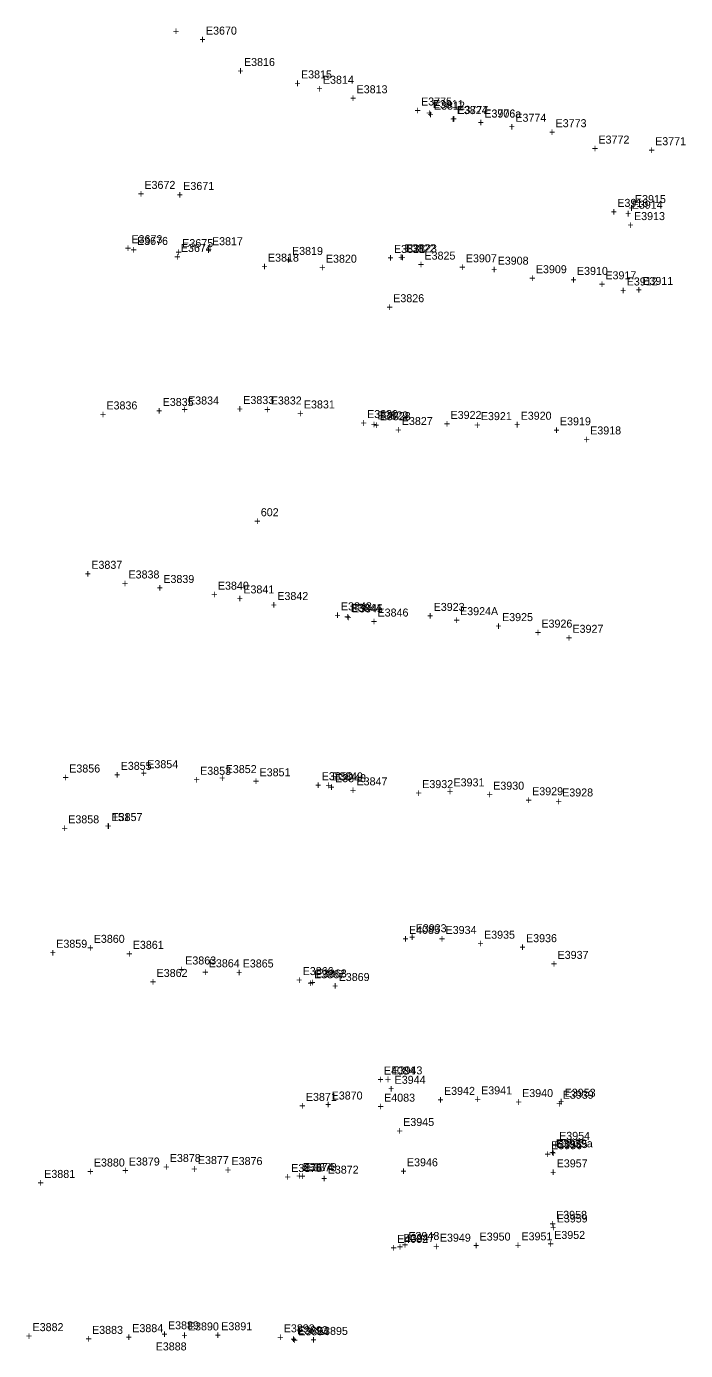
# Model space of a CAD drawing. Extents: x 1667192 to 1669644, y 336680 to 339991.
# Drawn here: x 1667196.6 to 1667402.6, y 337507.8 to 337921.4 of the extents above; entities that cross this region are included whole.
import ezdxf

# ---------------------------------------------------------------- set-up
doc = ezdxf.new("R2010")
doc.units = 0
for name, color, linetype in [('S_Control_Temp_Traverse', 7, 'Continuous'), ('S_Curb_Type_3', 7, 'Continuous'), ('S_Curb_Type_5', 7, 'Continuous'), ('S_Drainage_CB', 7, 'Continuous'), ('S_Ground_Elevation', 7, 'Continuous'), ('S_Guardrail_Beam', 7, 'Continuous'), ('S_Roadway_Edge_Pavement', 7, 'Continuous'), ('S_Roadway_Edge_TW', 7, 'Continuous'), ('S_Traffic_Sign_SinglePost', 7, 'Continuous'), ('S_Utilities_GuyWire3', 7, 'Continuous'), ('S_Utilities_Pole_Power', 7, 'Continuous')]:
    doc.layers.add(name, color=color, linetype=linetype)

msp = doc.modelspace()

# ---------------------------------------------------------------- texts
at = {"layer": 'S_Control_Temp_Traverse'}
for s, p in [('+', (1667267.8, 337765.64)), ('+', (1667267.8, 337765.64)), ('+', (1667267.8, 337765.64)), ('+', (1667267.8, 337765.64)), ('+', (1667267.8, 337765.64)), ('+', (1667267.8, 337765.64)), ('+', (1667267.8, 337765.64)), ('+', (1667267.8, 337765.64)), ('602', (1667269.86, 337768.39)), ('602', (1667269.86, 337768.39)), ('602', (1667269.86, 337768.39)), ('602', (1667269.86, 337768.39)), ('602', (1667269.86, 337768.39)), ('602', (1667269.86, 337768.39)), ('602', (1667269.86, 337768.39)), ('602', (1667269.86, 337768.39)), ('151', (1667223.37, 337673.16)), ('+', (1667221.31, 337670.41))]:
    msp.add_text(s, height=2.5, dxfattribs=at).set_placement(p)
at = {"layer": 'S_Curb_Type_3'}
for s, p in [('E3955', (1667362.31, 337571.02)), ('+', (1667360.25, 337568.27)), ('E3959', (1667362.32, 337547.79)), ('+', (1667360.26, 337545.04))]:
    msp.add_text(s, height=2.5, dxfattribs=at).set_placement(p)
at = {"layer": 'S_Curb_Type_5'}
for s, p in [('E3812', (1667323.96, 337895.39)), ('+', (1667321.9, 337892.64)), ('E3823', (1667315.22, 337850.78)), ('+', (1667313.16, 337848.03)), ('E3828', (1667307.01, 337798.39)), ('+', (1667304.95, 337795.64)), ('E3845', (1667298.32, 337738.34)), ('+', (1667296.26, 337735.59)), ('E3848', (1667293.05, 337685.32)), ('+', (1667290.99, 337682.57)), ('+', (1667284.97, 337621.56)), ('E3868', (1667287.03, 337624.31)), ('E3873', (1667283.92, 337563.79)), ('+', (1667281.86, 337561.04)), ('+', (1667279.49, 337509.8)), ('E3894', (1667281.55, 337512.55))]:
    msp.add_text(s, height=2.5, dxfattribs=at).set_placement(p)
at = {"layer": 'S_Drainage_CB'}
for s, p in [('E3915', (1667386.77, 337866.21)), ('+', (1667384.71, 337863.46)), ('+', (1667309.18, 337832.49)), ('E3826', (1667311.24, 337835.24)), ('E3871', (1667283.94, 337585.75)), ('E3870', (1667292, 337586.19)), ('+', (1667281.88, 337583)), ('+', (1667289.94, 337583.44)), ('+', (1667358.51, 337567.93)), ('E3956', (1667360.57, 337570.68))]:
    msp.add_text(s, height=2.5, dxfattribs=at).set_placement(p)
at = {"layer": 'S_Ground_Elevation'}
for s, p in [('+', (1667242.38, 337918.66)), ('E3670', (1667252.72, 337918.83)), ('+', (1667250.66, 337916.08)), ('+', (1667262.54, 337906.27)), ('E3816', (1667264.6, 337909.02)), ('+', (1667280.36, 337902.4)), ('E3815', (1667282.42, 337905.15)), ('E3824', (1667331.06, 337894)), ('E3777', (1667331.27, 337894.08)), ('+', (1667329, 337891.25)), ('+', (1667329.21, 337891.33)), ('E3672', (1667233.49, 337870.63)), ('E3671', (1667245.63, 337870.31)), ('+', (1667231.43, 337867.88)), ('+', (1667243.57, 337867.56)), ('E3673', (1667229.44, 337853.67)), ('E3817', (1667254.6, 337853.05)), ('+', (1667227.38, 337850.92)), ('E3674', (1667244.88, 337850.94)), ('+', (1667252.54, 337850.3)), ('E3818', (1667272.09, 337847.91)), ('E3825', (1667321, 337848.55)), ('+', (1667242.82, 337848.19)), ('+', (1667270.03, 337845.16)), ('+', (1667318.94, 337845.8)), ('E3835', (1667239.19, 337802.83)), ('E3834', (1667247.13, 337803.29)), ('E3833', (1667264.38, 337803.44)), ('+', (1667219.56, 337799)), ('E3836', (1667221.62, 337801.75)), ('+', (1667237.13, 337800.08)), ('+', (1667245.07, 337800.54)), ('+', (1667262.32, 337800.69)), ('E3827', (1667313.92, 337796.88)), ('+', (1667311.85, 337794.13)), ('+', (1667214.84, 337749.21)), ('E3837', (1667216.9, 337751.96)), ('E3838', (1667228.52, 337748.95)), ('+', (1667226.46, 337746.2)), ('E3839', (1667239.4, 337747.54)), ('E3840', (1667256.45, 337745.45)), ('+', (1667237.34, 337744.79)), ('+', (1667254.39, 337742.7)), ('E3846', (1667306.33, 337737.05)), ('+', (1667304.27, 337734.3)), ('E3856', (1667210, 337688.34)), ('E3855', (1667226.07, 337689.17)), ('E3854', (1667234.38, 337689.68)), ('E3853', (1667250.9, 337687.62)), ('+', (1667207.94, 337685.59)), ('+', (1667224.01, 337686.42)), ('+', (1667232.32, 337686.93)), ('+', (1667248.84, 337684.87)), ('E3847', (1667299.76, 337684.32)), ('+', (1667297.7, 337681.57)), ('E4085', (1667316.16, 337637.91)), ('E3859', (1667205.95, 337633.6)), ('E3860', (1667217.66, 337635.13)), ('E3861', (1667229.85, 337633.26)), ('+', (1667314.1, 337635.17)), ('+', (1667203.89, 337630.85)), ('+', (1667215.6, 337632.38)), ('+', (1667227.79, 337630.51)), ('+', (1667244.18, 337625.62)), ('E3863', (1667246.24, 337628.37)), ('E3869', (1667294.18, 337623.21)), ('+', (1667292.12, 337620.46)), ('E4084', (1667308.33, 337593.97)), ('+', (1667306.27, 337591.22)), ('E4083', (1667308.39, 337585.53)), ('+', (1667306.33, 337582.78)), ('E3880', (1667217.69, 337565.26)), ('E3879', (1667228.62, 337565.58)), ('+', (1667239.36, 337563.92)), ('E3878', (1667241.42, 337566.67)), ('E3872', (1667290.76, 337563.04)), ('+', (1667200.13, 337558.95)), ('E3881', (1667202.19, 337561.7)), ('+', (1667215.63, 337562.51)), ('+', (1667226.56, 337562.83)), ('+', (1667288.7, 337560.29)), ('+', (1667310.4, 337538.67)), ('E4082', (1667312.47, 337541.42)), ('E3882', (1667198.54, 337513.84)), ('E3883', (1667217.13, 337512.98)), ('E3884', (1667229.7, 337513.52)), ('E3889', (1667240.86, 337514.42)), ('+', (1667196.48, 337511.09)), ('+', (1667215.07, 337510.23)), ('+', (1667227.64, 337510.77)), ('+', (1667238.8, 337511.67)), ('+', (1667285.34, 337509.91)), ('E3895', (1667287.4, 337512.66))]:
    msp.add_text(s, height=2.5, dxfattribs=at).set_placement(p)
at = {"layer": 'S_Guardrail_Beam'}
for s, p in [('+', (1667309.61, 337588.35)), ('E3944', (1667311.67, 337591.1)), ('+', (1667362.75, 337584.31)), ('E3953', (1667364.81, 337587.06)), ('E3945', (1667314.35, 337577.92)), ('+', (1667312.29, 337575.17)), ('E3954', (1667363.07, 337573.59)), ('+', (1667361.01, 337570.84)), ('E3946', (1667315.52, 337565.34)), ('E3957', (1667362.31, 337565)), ('+', (1667313.46, 337562.59)), ('+', (1667360.25, 337562.25)), ('E3958', (1667362.12, 337548.92)), ('E3948', (1667315.98, 337542.32)), ('+', (1667360.06, 337546.17)), ('+', (1667313.92, 337539.57))]:
    msp.add_text(s, height=2.5, dxfattribs=at).set_placement(p)
at = {"layer": 'S_Roadway_Edge_Pavement'}
for s, p in [('E3814', (1667289.27, 337903.47)), ('+', (1667287.21, 337900.72)), ('E3811', (1667323.6, 337895.86)), ('+', (1667321.54, 337893.11)), ('+', (1667337.64, 337890.19)), ('+', (1667337.64, 337890.14)), ('E3776', (1667339.7, 337892.94)), ('E3906a', (1667339.7, 337892.89)), ('E3916', (1667381.26, 337865.02)), ('+', (1667379.2, 337862.27)), ('+', (1667383.68, 337861.69)), ('E3914', (1667385.75, 337864.44)), ('E3913', (1667386.48, 337860.89)), ('+', (1667384.42, 337858.14)), ('E3819', (1667279.61, 337850.01)), ('E3822', (1667314.79, 337850.81)), ('+', (1667277.55, 337847.26)), ('+', (1667312.73, 337848.06)), ('+', (1667331.86, 337844.96)), ('E3907', (1667333.92, 337847.71)), ('E3917', (1667377.53, 337842.4)), ('E3912', (1667384.18, 337840.47)), ('+', (1667375.47, 337839.65)), ('+', (1667382.11, 337837.72)), ('E3832', (1667272.97, 337803.29)), ('+', (1667270.91, 337800.54)), ('E3829', (1667306.29, 337798.62)), ('E3922', (1667329.15, 337798.78)), ('+', (1667304.23, 337795.87)), ('+', (1667327.09, 337796.03)), ('+', (1667370.72, 337791.19)), ('E3918', (1667372.78, 337793.94)), ('+', (1667262.34, 337741.53)), ('E3841', (1667264.4, 337744.28)), ('E3844', (1667297.98, 337738.52)), ('E3923', (1667323.87, 337738.81)), ('+', (1667295.92, 337735.77)), ('+', (1667321.81, 337736.06)), ('+', (1667365.18, 337729.22)), ('E3927', (1667367.24, 337731.97)), ('E3852', (1667258.89, 337688.15)), ('+', (1667256.83, 337685.4)), ('+', (1667290.07, 337683.12)), ('E3849', (1667292.13, 337685.87)), ('E3932', (1667320.3, 337683.47)), ('+', (1667318.24, 337680.72)), ('E3928', (1667364.03, 337680.85)), ('+', (1667361.97, 337678.1)), ('E3933', (1667318.24, 337638.45)), ('+', (1667316.18, 337635.7)), ('E3937', (1667362.59, 337630.11)), ('E3864', (1667253.6, 337627.5)), ('+', (1667360.52, 337627.36)), ('+', (1667251.54, 337624.75)), ('+', (1667284.45, 337621.31)), ('E3867', (1667286.51, 337624.06)), ('E3943', (1667310.67, 337594.04)), ('+', (1667308.6, 337591.29)), ('+', (1667362.14, 337583.68)), ('E3939', (1667364.2, 337586.43)), ('E3939a', (1667362.05, 337571.24)), ('+', (1667359.99, 337568.49)), ('+', (1667248.14, 337563.28)), ('E3877', (1667250.2, 337566.03)), ('E3874', (1667282.95, 337563.86)), ('+', (1667280.89, 337561.11)), ('E3952', (1667361.53, 337542.64)), ('+', (1667312.4, 337538.97)), ('E3947', (1667314.46, 337541.72)), ('+', (1667359.47, 337539.89)), ('E3890', (1667247.09, 337514.07)), ('+', (1667245.03, 337511.32)), ('+', (1667279.11, 337510.13)), ('E3893', (1667281.17, 337512.88))]:
    msp.add_text(s, height=2.5, dxfattribs=at).set_placement(p)
at = {"layer": 'S_Roadway_Edge_TW'}
for s, p in [('E3813', (1667299.79, 337900.51)), ('+', (1667297.73, 337897.76)), ('+', (1667317.87, 337893.93)), ('E3775', (1667319.93, 337896.68)), ('E3774', (1667349.4, 337891.61)), ('E3773', (1667361.97, 337889.91)), ('+', (1667347.33, 337888.86)), ('+', (1667359.91, 337887.16)), ('+', (1667373.3, 337882.04)), ('E3772', (1667375.36, 337884.79)), ('+', (1667391.01, 337881.54)), ('E3771', (1667393.07, 337884.29)), ('E3821', (1667311.47, 337850.63)), ('+', (1667288.14, 337844.83)), ('E3820', (1667290.2, 337847.58)), ('+', (1667309.41, 337847.88)), ('+', (1667341.8, 337844.22)), ('E3908', (1667343.86, 337846.97)), ('E3909', (1667355.8, 337844.3)), ('E3910', (1667368.64, 337843.77)), ('+', (1667353.74, 337841.55)), ('+', (1667366.58, 337841.02)), ('E3911', (1667389.07, 337840.63)), ('+', (1667387.01, 337837.88)), ('+', (1667281.26, 337799.31)), ('E3831', (1667283.32, 337802.06)), ('E3830', (1667303.07, 337799.05)), ('E3921', (1667338.62, 337798.41)), ('E3920', (1667351.05, 337798.53)), ('+', (1667301.01, 337796.3)), ('+', (1667336.56, 337795.66)), ('+', (1667348.99, 337795.78)), ('E3919', (1667363.33, 337796.8)), ('+', (1667361.27, 337794.05)), ('E3842', (1667275.02, 337742.21)), ('+', (1667272.96, 337739.46)), ('E3843', (1667294.9, 337739)), ('E3924A', (1667332.12, 337737.49)), ('+', (1667292.84, 337736.25)), ('+', (1667330.06, 337734.74)), ('+', (1667343.17, 337732.88)), ('E3925', (1667345.24, 337735.63)), ('E3926', (1667357.54, 337733.6)), ('+', (1667355.48, 337730.85)), ('E3851', (1667269.47, 337687.16)), ('+', (1667267.41, 337684.41)), ('+', (1667286.82, 337683.18)), ('E3850', (1667288.89, 337685.93)), ('E3931', (1667330.07, 337684)), ('E3930', (1667342.48, 337682.97)), ('+', (1667328.01, 337681.25)), ('+', (1667340.42, 337680.22)), ('E3929', (1667354.64, 337681.23)), ('+', (1667352.58, 337678.48)), ('E3934', (1667327.59, 337637.91)), ('+', (1667325.53, 337635.16)), ('+', (1667337.55, 337633.67)), ('E3935', (1667339.61, 337636.42)), ('E3936', (1667352.73, 337635.34)), ('+', (1667350.67, 337632.59)), ('E3865', (1667264.2, 337627.44)), ('E3866', (1667282.95, 337625.06)), ('+', (1667262.14, 337624.69)), ('+', (1667280.89, 337622.31)), ('E3942', (1667327.1, 337587.64)), ('E3941', (1667338.7, 337587.8)), ('+', (1667325.04, 337584.89)), ('+', (1667336.64, 337585.05)), ('+', (1667349.45, 337584.21)), ('E3940', (1667351.51, 337586.96)), ('E3876', (1667260.71, 337565.72)), ('E3875', (1667279.35, 337563.55)), ('+', (1667258.65, 337562.97)), ('+', (1667277.29, 337560.8)), ('E3950', (1667338.23, 337542.13)), ('E3951', (1667351.3, 337542.2)), ('+', (1667323.74, 337539.04)), ('E3949', (1667325.81, 337541.79)), ('+', (1667336.17, 337539.38)), ('+', (1667349.24, 337539.45)), ('E3891', (1667257.51, 337514.12)), ('E3892', (1667277.03, 337513.47)), ('+', (1667255.45, 337511.37)), ('+', (1667274.97, 337510.72))]:
    msp.add_text(s, height=2.5, dxfattribs=at).set_placement(p)
at = {"layer": 'S_Traffic_Sign_SinglePost'}
for s, p in [('+', (1667235.23, 337621.73)), ('E3862', (1667237.3, 337624.48)), ('E3888', (1667237.01, 337507.82))]:
    msp.add_text(s, height=2.5, dxfattribs=at).set_placement(p)
at = {"layer": 'S_Utilities_GuyWire3'}
for s, p in [('E3676', (1667231.19, 337853.13)), ('+', (1667229.13, 337850.38)), ('E3858', (1667209.69, 337672.46)), ('+', (1667207.63, 337669.71))]:
    msp.add_text(s, height=2.5, dxfattribs=at).set_placement(p)
at = {"layer": 'S_Utilities_Pole_Power'}
for s, p in [('E3675', (1667245.3, 337852.44)), ('+', (1667243.24, 337849.69)), ('E3857', (1667223.21, 337673.17)), ('+', (1667221.15, 337670.42))]:
    msp.add_text(s, height=2.5, dxfattribs=at).set_placement(p)

doc.saveas('drawing.dxf')
